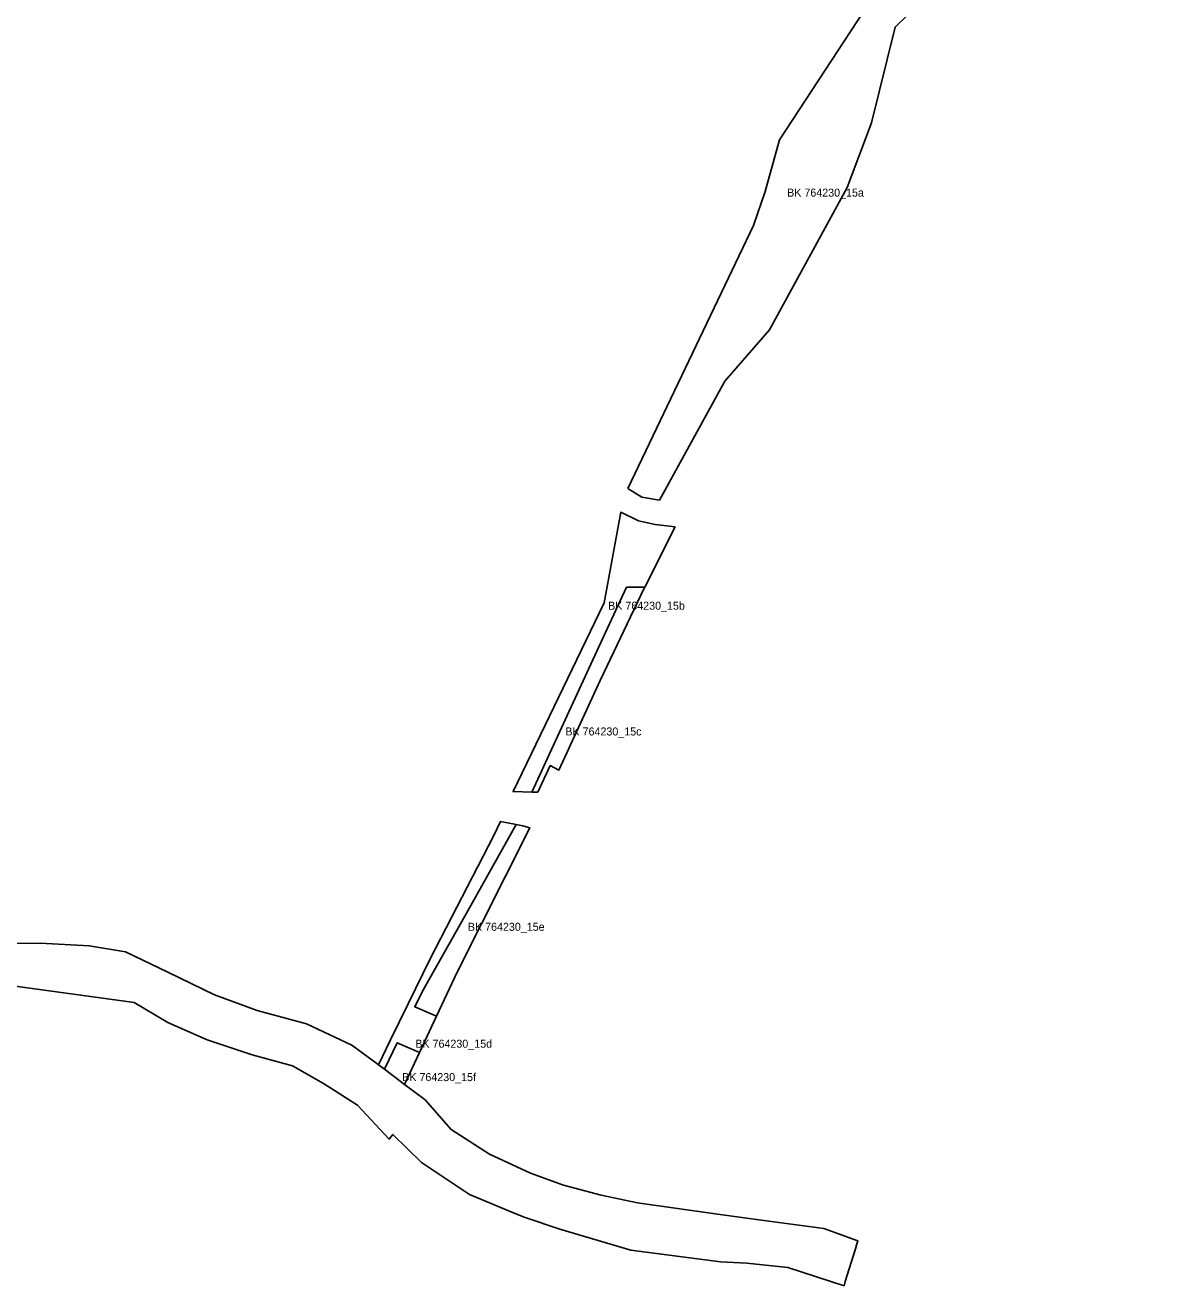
# Model space of a CAD drawing. Extents: x -521616 to -516782, y -1190061 to -1184927.
# Drawn here: x -517887 to -517316, y -1188053 to -1187423 of the extents above; entities that cross this region are included whole.
import ezdxf

# ---------------------------------------------------------------- set-up
doc = ezdxf.new("R2010")
doc.units = 0
doc.layers.add('LBK_n', color=7, linetype='Continuous')
doc.layers.add('LBK_s', color=7, linetype='Continuous')

msp = doc.modelspace()

# ---------------------------------------------------------------- linework, layer by layer
at = {"layer": 'LBK_n'}
for points in [[(-517586.42, -1187704.28), (-517601.22, -1187736.39), (-517633.65, -1187806.72), (-517643.05, -1187806.47), (-517597.6, -1187712.15), (-517589.23, -1187666.93), (-517580.33, -1187671.15), (-517572.04, -1187673.09)], [(-517562.02, -1187674.2), (-517577.22, -1187704.42), (-517586.42, -1187704.28)], [(-517572.04, -1187673.09), (-517562.02, -1187674.2)]]:
    msp.add_lwpolyline(points, dxfattribs=at)
msp.add_lwpolyline([(-517684.52, -1187890.12), (-517652.7, -1187828.42), (-517649.36, -1187821.4), (-517641.56, -1187823), (-517665.69, -1187866.1), (-517688.38, -1187906.23), (-517692.2, -1187914.02), (-517681.37, -1187918.78), (-517689.84, -1187936.9), (-517701, -1187932), (-517707.44, -1187945.15), (-517710.38, -1187943), (-517704.29, -1187930.56), (-517695.5, -1187912.58)], close=True, dxfattribs=at)
at = {"layer": 'LBK_s'}
for points in [[(-517585.65, -1187655.05), (-517522.89, -1187523.56), (-517517.01, -1187506.52), (-517509.93, -1187480.82), (-517441.74, -1187376.62), (-517361.78, -1187252.72), (-517351.69, -1187237.2), (-517316.22, -1187258.48), (-517347.39, -1187309.18), (-517384.09, -1187358.04), (-517452.09, -1187424.46), (-517463.8, -1187472.2), (-517475.96, -1187504.62), (-517514.92, -1187575.77), (-517537.21, -1187601.44), (-517569.92, -1187660.82), (-517578.63, -1187659.32), (-517585.65, -1187655.05)], [(-517681.37, -1187918.78), (-517692.2, -1187914.02), (-517688.38, -1187906.23), (-517665.69, -1187866.1), (-517641.56, -1187823), (-517638.28, -1187823.67), (-517634.71, -1187824.59), (-517671.09, -1187896.81)], [(-517701, -1187932), (-517689.84, -1187936.9), (-517697.3, -1187952.84), (-517707.44, -1187945.15)]]:
    msp.add_lwpolyline(points, close=True, dxfattribs=at)
for points in [[(-517577.22, -1187704.42), (-517577.46, -1187704.91), (-517599.53, -1187750.9), (-517620.19, -1187795.76), (-517624.53, -1187793.53), (-517630.7, -1187806.8), (-517633.65, -1187806.72), (-517601.22, -1187736.39), (-517586.42, -1187704.28)], [(-517586.42, -1187704.28), (-517577.22, -1187704.42)], [(-517899.42, -1187882.5), (-517879.51, -1187882.19), (-517854.97, -1187883.58), (-517836.92, -1187886.66), (-517815.62, -1187896.7), (-517792.32, -1187908.12), (-517771.02, -1187915.83), (-517746.33, -1187922.62), (-517723.64, -1187933.27), (-517707.44, -1187945.15), (-517697.3, -1187952.84), (-517693.54, -1187955.69), (-517687.07, -1187960.59), (-517674.1, -1187975.4), (-517654.81, -1187987.75), (-517634.29, -1187997.16), (-517617.93, -1188003.18), (-517598.95, -1188008.12), (-517580.89, -1188011.98), (-517542, -1188017.53), (-517517.62, -1188020.93), (-517487.68, -1188024.79), (-517470.7, -1188031.07), (-517471.13, -1188032.47), (-517471.9, -1188034.95), (-517476.96, -1188051.38), (-517477.6, -1188053.48), (-517477.6, -1188053.48), (-517505.73, -1188044.38), (-517526.26, -1188042.22), (-517539.38, -1188041.45), (-517584.13, -1188035.74), (-517619.78, -1188025.25), (-517637.07, -1188019.38), (-517641.69, -1188017.46), (-517664.84, -1188007.81), (-517688.92, -1187991.91), (-517703.12, -1187977.87), (-517704.97, -1187980.19), (-517720.86, -1187963.21), (-517737.84, -1187952.41), (-517753.43, -1187943.61), (-517773.49, -1187938.05), (-517796.02, -1187930.49), (-517815.77, -1187921.85), (-517832.59, -1187911.97), (-517900.65, -1187902.56)]]:
    msp.add_lwpolyline(points, dxfattribs=at)

# ---------------------------------------------------------------- texts
at = {"layer": 'LBK_n'}
for s, p in [('BK 764230_15b', (-517595.56, -1187715.6)), ('BK 764230_15d', (-517691.95, -1187934.5))]:
    msp.add_text(s, height=4, dxfattribs=at).set_placement(p)
at = {"layer": 'LBK_s'}
for s, p in [('BK 764230_15a', (-517506.04, -1187509.16)), ('BK 764230_15c', (-517616.94, -1187778.45)), ('BK 764230_15e', (-517665.68, -1187876.07)), ('BK 764230_15f', (-517698.52, -1187951.19))]:
    msp.add_text(s, height=4, dxfattribs=at).set_placement(p)

doc.saveas('drawing.dxf')
